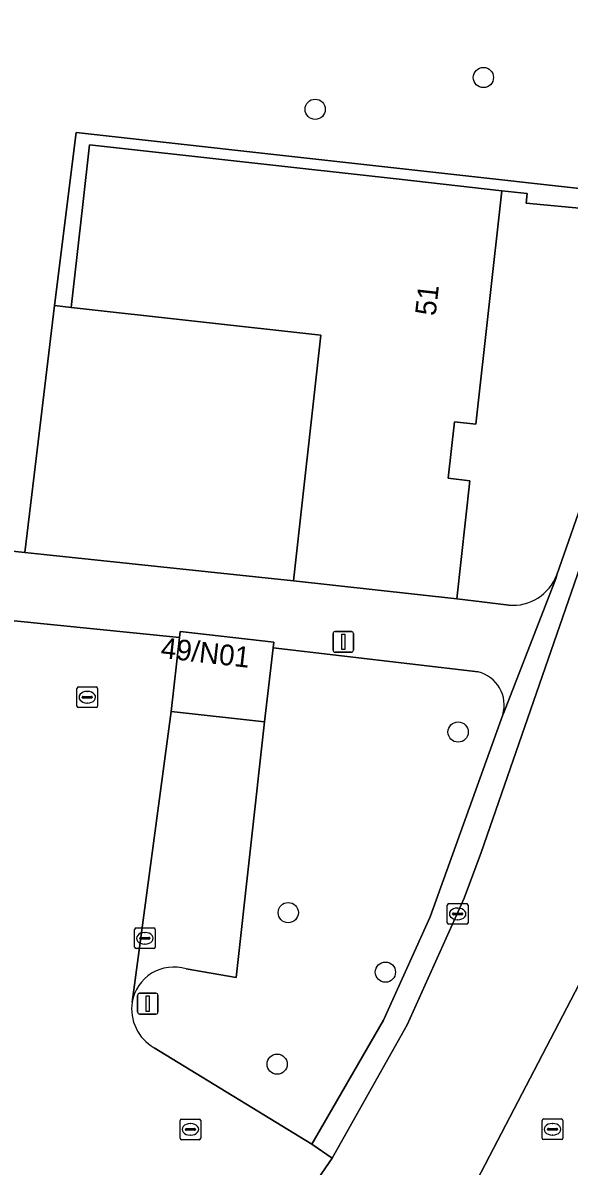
# Model space of a CAD drawing. Extents: x 162396 to 163643, y 386452 to 387406.
# Drawn here: x 162874.5 to 162900.9, y 386930.2 to 386985.4 of the extents above; entities that cross this region are included whole.
import ezdxf

# ---------------------------------------------------------------- set-up
doc = ezdxf.new("R2010")
doc.units = 0
for name, color, linetype in [('IMGEO_Boom', 7, 'Continuous'), ('IMGEO_Erf', 7, 'Continuous'), ('IMGEO_Groenvoorziening', 7, 'Continuous'), ('IMGEO_Haag', 7, 'Continuous'), ('IMGEO_Kolk', 7, 'Continuous'), ('IMGEO_Lichtmast', 7, 'Continuous'), ('IMGEO_Muur', 7, 'Continuous'), ('IMGEO_Pand', 7, 'Continuous'), ('IMGEO_Pand_nummerreeks', 7, 'Continuous'), ('IMGEO_Parkeervlak_open', 7, 'Continuous'), ('IMGEO_Rijbaan_lokaal_open', 7, 'Continuous'), ('IMGEO_Rioolput', 7, 'Continuous'), ('IMGEO_Voetpad_open', 7, 'Continuous')]:
    doc.layers.add(name, color=color, linetype=linetype)

msp = doc.modelspace()

# ---------------------------------------------------------------- linework, layer by layer
at = {"layer": 'IMGEO_Boom'}
for centre in [(162896.793, 386982.798), (162888.656, 386981.262), (162895.569, 386951.153), (162887.351, 386942.42), (162892.053, 386939.544), (162886.814, 386935.093)]:
    msp.add_circle(centre, 0.489, dxfattribs=at)
at = {"layer": 'IMGEO_Erf'}
for points in [[(162904.623, 386970.887), (162905.487, 386973.848), (162906.409, 386976.073), (162905.02, 386976.148), (162898.862, 386976.722), (162898.914, 386977.188), (162897.692, 386977.322), (162896.433, 386966.033), (162895.395, 386966.149), (162895.091, 386963.422), (162896.141, 386963.305), (162895.504, 386957.59), (162896.723, 386957.446), (162898.025, 386957.293)], [(162900.342, 386958.755), (162901.853, 386963.037), (162902.204, 386964.031), (162904.623, 386970.887)]]:
    msp.add_lwpolyline(points, dxfattribs=at)
msp.add_lwpolyline([(162887.607, 386958.47), (162888.929, 386970.338), (162876.857, 386971.684), (162876.045, 386971.774), (162875.105, 386963.974), (162874.608, 386959.841), (162875.527, 386959.744)], close=True, dxfattribs=at)
msp.add_arc((162898.233, 386959.53), 2.247, 264.69, 339.8129, dxfattribs=at)
at = {"layer": 'IMGEO_Groenvoorziening'}
for points in [[(162867.707, 386960.569), (162874.608, 386959.841), (162875.105, 386963.974), (162876.045, 386971.774), (162877.089, 386980.146), (162905.357, 386976.996)], [(162896.534, 386954.056), (162886.615, 386955.228), (162886.363, 386953.015), (162886.207, 386951.639), (162884.831, 386939.284), (162882.408, 386939.7)], [(162880.863, 386935.89), (162888.485, 386931.218), (162891.957, 386937.22), (162894.215, 386942.213), (162897.727, 386951.991)]]:
    msp.add_lwpolyline(points, dxfattribs=at)
msp.add_lwpolyline([(162877.089, 386980.146), (162876.045, 386971.774), (162876.857, 386971.684), (162877.411, 386976.654), (162877.733, 386979.546), (162892.723, 386977.876), (162897.692, 386977.322), (162898.914, 386977.188), (162898.862, 386976.722), (162905.02, 386976.148), (162905.357, 386976.996)], close=True, dxfattribs=at)
for centre, radius, start, end in [((162896.166, 386952.467), 1.631, 343.0528, 76.9793), ((162881.808, 386937.747), 2.043, 72.9251, 170.1184), ((162881.934, 386937.769), 2.163, 171.2541, 240.3296)]:
    msp.add_arc(centre, radius, start, end, dxfattribs=at)
at = {"layer": 'IMGEO_Haag'}
msp.add_lwpolyline([(162877.089, 386980.146), (162876.045, 386971.774), (162876.857, 386971.684), (162877.411, 386976.654), (162877.733, 386979.546), (162892.723, 386977.876), (162897.692, 386977.322), (162898.914, 386977.188), (162898.862, 386976.722), (162905.02, 386976.148), (162905.357, 386976.996)], close=True, dxfattribs=at)
at = {"layer": 'IMGEO_Kolk'}
for p, q in [((162895.047, 386941.932), (162895.047, 386942.784)), ((162895.122, 386942.858), (162895.974, 386942.858)), ((162895.535, 386942.638), (162895.56, 386942.638)), ((162896.048, 386942.784), (162896.048, 386941.932)), ((162895.306, 386942.352), (162895.306, 386942.364)), ((162895.744, 386942.315), (162895.346, 386942.315)), ((162895.349, 386942.401), (162895.747, 386942.401)), ((162895.558, 386942.078), (162895.533, 386942.078)), ((162895.79, 386942.364), (162895.79, 386942.352)), ((162879.915, 386940.755), (162879.915, 386941.607)), ((162879.99, 386941.681), (162880.842, 386941.681)), ((162880.403, 386941.461), (162880.428, 386941.461)), ((162880.916, 386941.607), (162880.916, 386940.755)), ((162895.974, 386941.858), (162895.122, 386941.858)), ((162880.174, 386941.175), (162880.174, 386941.187)), ((162880.612, 386941.138), (162880.214, 386941.138)), ((162880.217, 386941.224), (162880.615, 386941.224)), ((162880.426, 386940.901), (162880.401, 386940.901)), ((162880.658, 386941.187), (162880.658, 386941.175)), ((162880.842, 386940.681), (162879.99, 386940.681)), ((162882.116, 386931.514), (162882.116, 386932.366)), ((162882.191, 386932.44), (162883.043, 386932.44)), ((162882.604, 386932.22), (162882.629, 386932.22)), ((162883.117, 386932.366), (162883.117, 386931.514)), ((162882.375, 386931.934), (162882.375, 386931.946)), ((162882.813, 386931.897), (162882.415, 386931.897)), ((162882.418, 386931.983), (162882.816, 386931.983)), ((162882.627, 386931.66), (162882.602, 386931.66)), ((162882.859, 386931.946), (162882.859, 386931.934)), ((162883.043, 386931.44), (162882.191, 386931.44))]:
    msp.add_line(p, q, dxfattribs=at)
for points in [[(162895.047, 386941.932), (162895.047, 386942.784)], [(162895.122, 386942.858), (162895.974, 386942.858)], [(162896.048, 386942.784), (162896.048, 386941.932)], [(162879.915, 386940.755), (162879.915, 386941.607)], [(162879.99, 386941.681), (162880.842, 386941.681)], [(162880.916, 386941.607), (162880.916, 386940.755)], [(162895.974, 386941.858), (162895.122, 386941.858)], [(162880.842, 386940.681), (162879.99, 386940.681)], [(162882.116, 386931.514), (162882.116, 386932.366)], [(162882.191, 386932.44), (162883.043, 386932.44)], [(162883.117, 386932.366), (162883.117, 386931.514)], [(162883.043, 386931.44), (162882.191, 386931.44)]]:
    msp.add_lwpolyline(points, dxfattribs=at)
for centre, radius, start, end in [((162895.124, 386942.782), 0.0765, 91.552, 178.448), ((162895.124, 386942.782), 0.0765, 91.552, 178.448), ((162895.972, 386942.782), 0.0765, 1.552, 88.448), ((162895.972, 386942.782), 0.0765, 1.552, 88.448), ((162895.346, 386942.361), 0.0403, 85.8775, 175.7526), ((162895.343, 386942.351), 0.0366, 178.938, 274.7102), ((162895.747, 386942.358), 0.043, 264.8664, 352.4533), ((162895.751, 386942.363), 0.0386, 1.7309, 96.639), ((162879.992, 386941.605), 0.0765, 91.552, 178.448), ((162879.992, 386941.605), 0.0765, 91.552, 178.448), ((162880.84, 386941.605), 0.0765, 1.552, 88.448), ((162880.84, 386941.605), 0.0765, 1.552, 88.448), ((162895.124, 386941.934), 0.0765, 181.552, 268.448), ((162895.124, 386941.934), 0.0765, 181.552, 268.448), ((162895.972, 386941.934), 0.0765, 271.552, 358.448), ((162895.972, 386941.934), 0.0765, 271.552, 358.448), ((162880.214, 386941.184), 0.0403, 85.8775, 175.7526), ((162880.211, 386941.174), 0.0366, 178.938, 274.7102), ((162880.615, 386941.181), 0.043, 264.8664, 352.4533), ((162880.619, 386941.186), 0.0386, 1.7309, 96.639), ((162879.992, 386940.757), 0.0765, 181.552, 268.448), ((162879.992, 386940.757), 0.0765, 181.552, 268.448), ((162880.84, 386940.757), 0.0765, 271.552, 358.448), ((162880.84, 386940.757), 0.0765, 271.552, 358.448), ((162882.193, 386932.364), 0.0765, 91.552, 178.448), ((162882.193, 386932.364), 0.0765, 91.552, 178.448), ((162883.041, 386932.364), 0.0765, 1.552, 88.448), ((162883.041, 386932.364), 0.0765, 1.552, 88.448), ((162882.193, 386931.516), 0.0765, 181.552, 268.448), ((162882.193, 386931.516), 0.0765, 181.552, 268.448), ((162882.415, 386931.943), 0.0403, 85.8775, 175.7526), ((162882.412, 386931.933), 0.0366, 178.938, 274.7102), ((162882.816, 386931.94), 0.043, 264.8664, 352.4533), ((162882.82, 386931.945), 0.0386, 1.7309, 96.639), ((162883.041, 386931.516), 0.0765, 271.552, 358.448), ((162883.041, 386931.516), 0.0765, 271.552, 358.448)]:
    msp.add_arc(centre, radius, start, end, dxfattribs=at)
for centre, major_axis, ratio, start_param, end_param in [((162895.534, 386942.358), (-0.387, 0.002), 0.722429, 4.712389, 7.853982), ((162895.559, 386942.358), (-0.39, 0.002), 0.717154, 1.570796, 4.712389), ((162880.402, 386941.181), (-0.387, 0.002), 0.722429, 4.712389, 7.853982), ((162880.427, 386941.181), (-0.39, 0.002), 0.717154, 1.570796, 4.712389), ((162882.603, 386931.94), (-0.387, 0.002), 0.722429, 4.712389, 7.853982), ((162882.628, 386931.94), (-0.39, 0.002), 0.717154, 1.570796, 4.712389)]:
    msp.add_ellipse(centre, major_axis=major_axis, ratio=ratio, start_param=start_param, end_param=end_param, dxfattribs=at)
at = {"layer": 'IMGEO_Lichtmast'}
for p, q in [((162889.517, 386955.113), (162889.517, 386955.913)), ((162889.517, 386955.913), (162889.517, 386955.113)), ((162889.617, 386956.013), (162890.407, 386956.013)), ((162890.407, 386956.013), (162889.617, 386956.013)), ((162890.507, 386955.913), (162890.507, 386955.113)), ((162890.507, 386955.113), (162890.507, 386955.913)), ((162890.407, 386955.013), (162889.617, 386955.013)), ((162889.617, 386955.013), (162890.407, 386955.013)), ((162880.06, 386937.619), (162880.06, 386938.419)), ((162880.06, 386938.419), (162880.06, 386937.619)), ((162880.16, 386938.519), (162880.95, 386938.519)), ((162880.95, 386938.519), (162880.16, 386938.519)), ((162881.05, 386938.419), (162881.05, 386937.619)), ((162881.05, 386937.619), (162881.05, 386938.419)), ((162880.95, 386937.519), (162880.16, 386937.519)), ((162880.16, 386937.519), (162880.95, 386937.519))]:
    msp.add_line(p, q, dxfattribs=at)
for points in [[(162889.937, 386955.888), (162890.087, 386955.888), (162890.087, 386955.138), (162889.937, 386955.138), (162889.937, 386955.888)], [(162880.48, 386938.394), (162880.63, 386938.394), (162880.63, 386937.644), (162880.48, 386937.644), (162880.48, 386938.394)]]:
    msp.add_lwpolyline(points, dxfattribs=at)
for centre, start, end in [((162889.617, 386955.913), 90, 180), ((162889.617, 386955.913), 90, 180), ((162890.407, 386955.913), 0, 90), ((162890.407, 386955.913), 360, 90), ((162889.617, 386955.113), 180, 270), ((162889.617, 386955.113), 180, 270), ((162890.407, 386955.113), 270, 0), ((162890.407, 386955.113), 270, 0), ((162880.16, 386938.419), 90, 180), ((162880.16, 386938.419), 90, 180), ((162880.95, 386938.419), 0, 90), ((162880.95, 386938.419), 360, 90), ((162880.16, 386937.619), 180, 270), ((162880.16, 386937.619), 180, 270), ((162880.95, 386937.619), 270, 0), ((162880.95, 386937.619), 270, 0)]:
    msp.add_arc(centre, 0.1, start, end, dxfattribs=at)
at = {"layer": 'IMGEO_Muur'}
msp.add_lwpolyline([(162875.527, 386959.744), (162887.607, 386958.47)], dxfattribs=at)
at = {"layer": 'IMGEO_Pand'}
for points in [[(162895.504, 386957.59), (162896.141, 386963.305), (162895.091, 386963.422), (162895.395, 386966.149), (162896.433, 386966.033), (162897.692, 386977.322), (162892.723, 386977.876), (162877.733, 386979.546), (162877.411, 386976.654), (162876.857, 386971.684), (162888.929, 386970.338), (162887.607, 386958.47)], [(162886.615, 386955.228), (162886.646, 386955.499), (162882.127, 386956.013), (162882.094, 386955.725), (162881.688, 386952.153), (162886.207, 386951.639), (162886.363, 386953.015)]]:
    msp.add_lwpolyline(points, close=True, dxfattribs=at)
at = {"layer": 'IMGEO_Parkeervlak_open'}
for points in [[(162886.207, 386951.639), (162881.688, 386952.153), (162879.796, 386938.098)], [(162882.408, 386939.7), (162884.831, 386939.284), (162886.207, 386951.639)]]:
    msp.add_lwpolyline(points, dxfattribs=at)
msp.add_arc((162881.808, 386937.747), 2.043, 72.9251, 170.1184, dxfattribs=at)
at = {"layer": 'IMGEO_Rijbaan_lokaal_open'}
for points in [[(162905.275, 386970.114), (162896.686, 386945.321), (162895.855, 386943.119), (162893.112, 386936.994), (162889.469, 386930.55), (162886.5, 386926.213), (162886.42, 386926.104), (162880.904, 386918.631), (162876.426, 386912.565), (162865.209, 386897.338), (162862.122, 386893.167), (162861.282, 386892.024), (162858.659, 386888.439), (162838.248, 386860.664)], [(162879.796, 386938.098), (162881.688, 386952.153), (162882.094, 386955.725), (162873.936, 386956.547), (162871.058, 386929.777), (162881.539, 386928.863), (162885.569, 386926.725), (162886.5, 386926.213), (162889.469, 386930.55), (162888.485, 386931.218), (162880.863, 386935.89)], [(162843.687, 386856.331), (162855.142, 386871.885), (162857.371, 386874.915), (162862.085, 386881.321), (162864.331, 386884.373), (162869.41, 386891.274), (162875.27, 386899.237), (162893.927, 386924.59), (162901.627, 386939.333)], [(162901.627, 386939.333), (162893.927, 386924.59)]]:
    msp.add_lwpolyline(points, dxfattribs=at)
msp.add_arc((162881.934, 386937.769), 2.163, 171.2541, 240.3296, dxfattribs=at)
at = {"layer": 'IMGEO_Rioolput'}
for p, q in [((162877.129, 386952.409), (162877.129, 386953.261)), ((162877.204, 386953.335), (162878.056, 386953.335)), ((162877.617, 386953.115), (162877.642, 386953.115)), ((162878.13, 386953.261), (162878.13, 386952.409)), ((162877.388, 386952.829), (162877.388, 386952.841)), ((162877.826, 386952.792), (162877.428, 386952.792)), ((162877.431, 386952.878), (162877.829, 386952.878)), ((162877.64, 386952.555), (162877.615, 386952.555)), ((162877.872, 386952.841), (162877.872, 386952.829)), ((162878.056, 386952.335), (162877.204, 386952.335)), ((162899.635, 386931.52), (162899.635, 386932.372)), ((162899.71, 386932.446), (162900.562, 386932.446)), ((162900.123, 386932.226), (162900.148, 386932.226)), ((162900.636, 386932.372), (162900.636, 386931.52)), ((162900.562, 386931.446), (162899.71, 386931.446)), ((162899.894, 386931.94), (162899.894, 386931.952)), ((162900.332, 386931.903), (162899.934, 386931.903)), ((162899.937, 386931.989), (162900.335, 386931.989)), ((162900.146, 386931.666), (162900.121, 386931.666)), ((162900.378, 386931.952), (162900.378, 386931.94))]:
    msp.add_line(p, q, dxfattribs=at)
for points in [[(162877.129, 386952.409), (162877.129, 386953.261)], [(162877.204, 386953.335), (162878.056, 386953.335)], [(162878.13, 386953.261), (162878.13, 386952.409)], [(162878.056, 386952.335), (162877.204, 386952.335)], [(162899.635, 386931.52), (162899.635, 386932.372)], [(162899.71, 386932.446), (162900.562, 386932.446)], [(162900.636, 386932.372), (162900.636, 386931.52)], [(162900.562, 386931.446), (162899.71, 386931.446)]]:
    msp.add_lwpolyline(points, dxfattribs=at)
for centre, radius, start, end in [((162877.206, 386953.259), 0.0765, 91.552, 178.448), ((162877.206, 386953.259), 0.0765, 91.552, 178.448), ((162878.054, 386953.259), 0.0765, 1.552, 88.448), ((162878.054, 386953.259), 0.0765, 1.552, 88.448), ((162877.428, 386952.838), 0.0403, 85.8775, 175.7526), ((162877.425, 386952.828), 0.0366, 178.938, 274.7102), ((162877.829, 386952.835), 0.043, 264.8664, 352.4533), ((162877.833, 386952.84), 0.0386, 1.7309, 96.639), ((162877.206, 386952.411), 0.0765, 181.552, 268.448), ((162877.206, 386952.411), 0.0765, 181.552, 268.448), ((162878.054, 386952.411), 0.0765, 271.552, 358.448), ((162878.054, 386952.411), 0.0765, 271.552, 358.448), ((162899.712, 386932.37), 0.0765, 91.552, 178.448), ((162899.712, 386932.37), 0.0765, 91.552, 178.448), ((162900.56, 386932.37), 0.0765, 1.552, 88.448), ((162900.56, 386932.37), 0.0765, 1.552, 88.448), ((162899.712, 386931.522), 0.0765, 181.552, 268.448), ((162899.712, 386931.522), 0.0765, 181.552, 268.448), ((162899.934, 386931.949), 0.0403, 85.8775, 175.7526), ((162899.931, 386931.939), 0.0366, 178.938, 274.7102), ((162900.335, 386931.946), 0.043, 264.8664, 352.4533), ((162900.339, 386931.951), 0.0386, 1.7309, 96.639), ((162900.56, 386931.522), 0.0765, 271.552, 358.448), ((162900.56, 386931.522), 0.0765, 271.552, 358.448)]:
    msp.add_arc(centre, radius, start, end, dxfattribs=at)
for centre, major_axis, ratio, start_param, end_param in [((162877.616, 386952.835), (-0.387, 0.002), 0.722429, 4.712389, 7.853982), ((162877.641, 386952.835), (-0.39, 0.002), 0.717154, 1.570796, 4.712389), ((162900.122, 386931.946), (-0.387, 0.002), 0.722429, 4.712389, 7.853982), ((162900.147, 386931.946), (-0.39, 0.002), 0.717154, 1.570796, 4.712389)]:
    msp.add_ellipse(centre, major_axis=major_axis, ratio=ratio, start_param=start_param, end_param=end_param, dxfattribs=at)
at = {"layer": 'IMGEO_Voetpad_open'}
msp.add_lwpolyline([(162905.275, 386970.114), (162904.746, 386970.311), (162906.15, 386974.045), (162906.632, 386973.865), (162909.331, 386979.699), (162912.089, 386984.831), (162911.138, 386985.441), (162908.397, 386980.273), (162906.409, 386976.073), (162905.487, 386973.848), (162904.623, 386970.887), (162902.204, 386964.031), (162901.853, 386963.037), (162900.342, 386958.755), (162900.308, 386958.601), (162897.761, 386952.042), (162897.727, 386951.991), (162894.215, 386942.213), (162891.957, 386937.22), (162888.485, 386931.218), (162889.469, 386930.55), (162893.112, 386936.994), (162895.855, 386943.119), (162896.686, 386945.321)], close=True, dxfattribs=at)
for points in [[(162828.227, 386970.528), (162817.251, 386977.344), (162817.034, 386976.923), (162815.907, 386975.225), (162815.68, 386974.834), (162831.565, 386964.807), (162831.24, 386961.405), (162873.936, 386956.547), (162882.094, 386955.725), (162882.127, 386956.013), (162886.646, 386955.499), (162886.615, 386955.228), (162896.534, 386954.056)], [(162898.025, 386957.293), (162896.723, 386957.446), (162895.504, 386957.59), (162887.607, 386958.47), (162875.527, 386959.744), (162874.608, 386959.841), (162867.707, 386960.569), (162835.609, 386963.955), (162836.549, 386965.361), (162828.227, 386970.528)], [(162897.727, 386951.991), (162897.761, 386952.042), (162900.308, 386958.601), (162900.342, 386958.755)]]:
    msp.add_lwpolyline(points, dxfattribs=at)
for centre, radius, start, end in [((162898.233, 386959.53), 2.247, 264.69, 339.8129), ((162896.166, 386952.467), 1.631, 343.0528, 76.9793)]:
    msp.add_arc(centre, radius, start, end, dxfattribs=at)

# ---------------------------------------------------------------- texts
at = {"layer": 'IMGEO_Pand_nummerreeks'}
for s, rotation, p in [('51', 83.6364, (162894.478, 386971.248)), ('49/N01', 353.5657, (162881.153, 386954.74))]:
    msp.add_text(s, height=1, rotation=rotation, dxfattribs=at).set_placement(p)

doc.saveas('drawing.dxf')
